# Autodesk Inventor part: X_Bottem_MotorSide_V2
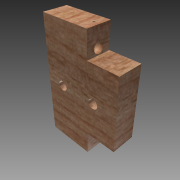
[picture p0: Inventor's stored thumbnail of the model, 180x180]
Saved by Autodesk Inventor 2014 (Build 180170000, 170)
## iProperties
Created: 2013-12
Part Number: X_Bottem_MotorSide_V2
Material: Birch
Document SubType Name: Modeling
Designer: Bram
Density: 0.512 g/cm^3
Appearance: Birch - Natural Medium Gloss
Author: Bram
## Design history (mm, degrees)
sketch "Sketch1"
  geometry: L1 (0, 0)-(60, 0); L2 (60, 0)-(60, 100); L3 (60, 100)-(0, 100); L4 (0, 100)-(0, 0); C1 r 4 at (15, 50); C2 r 4 at (45, 50)
  constraints: 8 end point, 2 centre point, 2 parallel, 1 horizontal, 1 perpendicular
  dimensions: "d0" = 60 distance of L3.end L2.end; "d1" = 100 distance of L2.end L1.end; "d4" = 8 diameter of C1; "d5" = 8 diameter of C2
extrude "Extrusion1" new body sketch "Sketch1" distance "d6" = 20; taper "d7" = 0 deg
sketch "Sketch2"
  geometry: L1 (0, 20)-(100, 20) reference; L2 (0, 0)-(0, 20) reference; L3 (50, 20)-(50, 10); L4 (50, 10)-(85, 10); L5 (50, 10)-(15, 10); C1 r 4 at (15, 10); C2 r 4 at (85, 10)
  constraints: 6 end point, 2 centre point, 2 coincident, 1 collinear, 1 midpoint, 1 parallel, 1 perpendicular
  dimensions: "d8" = 35 distance of L3.end L4.end; "d9" = 35 distance of L3.end L5.end; "d10" = 8 diameter of C1; "d11" = 8 diameter of C2
extrude "Extrusion2" cut sketch "Sketch2" distance "d12" = 80; taper "d13" = 0 deg
sketch "Sketch3"
  geometry: L1 (0, 0)-(100, 0) reference; L2 (100, 0)-(100, 20) reference; L3 (0, 20)-(100, 20) reference; L4 (0, 0)-(0, 20) reference; C1 r 4 at (15, 10) reference; C2 r 4 at (85, 10) reference
extrude "Extrusion3" join sketch "Sketch3" distance "d14" = 5; taper "d15" = 0 deg
sketch "Sketch4"
  geometry: L1 (5, 100)-(5, 0) reference; L2 (-60, 100)-(5, 100) reference; L3 (-60, 100)-(-20, 100); L4 (5, 50)-(-20, 50); L5 (-20, 50)-(-20, 80); L6 (-20, 50)-(-20, 20); L7 (-20, 20)-(5, 20); L8 (-20, 80)-(5, 80); L9 (-20, 80)-(5, 80); L10 (5, 80)-(5, 100); L11 (5, 100)-(-20, 100); L12 (-20, 100)-(-20, 80); L13 (-20, 20)-(5, 20); L14 (5, 20)-(5, 0); L15 (5, 0)-(-20, 0); L16 (-20, 0)-(-20, 20); 1 further point
  constraints: 28 end point, 5 parallel, 5 perpendicular, 3 point on line, 2 horizontal, 1 collinear, 1 midpoint
  dimensions: "d16" = 40 distance of L2.start L3.end; "d17" = 30 distance of L4.end L5.end; "d18" = 30 distance of L4.end L6.end
extrude "Extrusion4" cut sketch "Sketch4" distance "d19" = 20; taper "d20" = 0 deg
body "Solid1"
